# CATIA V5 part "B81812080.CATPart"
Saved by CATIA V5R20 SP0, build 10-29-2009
Part number: B81812080
Revision: 3
Definition: design
Nomenclature: B81812080
Source: made
Description: NOT SPECIFIED
Bounding box of the stored display mesh (mm): x -8 to 8, y -8 to 8, z 0 to 80
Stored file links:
  C:\Users\Raffaele\Desktop\3D X SITO CF\BOLEX\6-PILLAR REF 818\B81812080.CATPart
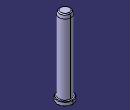
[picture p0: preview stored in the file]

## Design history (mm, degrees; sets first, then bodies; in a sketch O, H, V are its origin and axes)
Body1 "MANIFOLD_SOLID_BREP #370" (main body)
  Solid1: solid without history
